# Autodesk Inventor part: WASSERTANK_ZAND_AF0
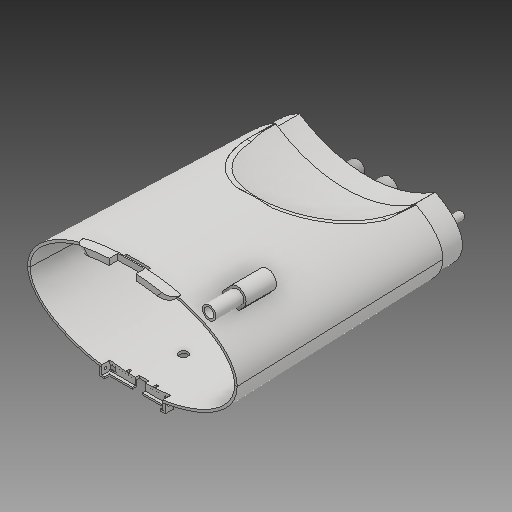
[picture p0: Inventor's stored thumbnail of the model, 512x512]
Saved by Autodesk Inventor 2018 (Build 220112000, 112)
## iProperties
Created: 2019-01
Part Number: WASSERTANK_ZAND_AF0
Material: Polypropylene (PP)
Document SubType Name: Modeling
Designer: zand
Density: 0.902188 g/cm^3
Appearance: Vorgabe
Mass: 158.687 g
Surface Area: 1788.25 cm^2
Volume: 175.892 cm^3
Author: zand
Revision Number: 53LAST_VERSION
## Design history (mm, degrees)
feature "Basis1"
feature "Basis2"
feature "Basis3"
feature "Basis4"
feature "Basis5"
node "Volumenkörper1"
node "Volumenkörper2"
node "Volumenkörper3"
node "Volumenkörper4"
node "Volumenkörper5"
